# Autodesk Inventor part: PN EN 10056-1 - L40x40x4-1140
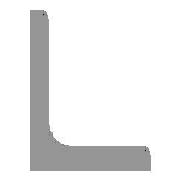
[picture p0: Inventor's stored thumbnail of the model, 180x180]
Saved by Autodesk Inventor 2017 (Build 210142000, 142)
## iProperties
IsCustomPart: 1
Created: 2020-07
Part Number: PN EN 10056-1 - L40x40x4-1140
Material: Stal, miękka
Description: Kątownik równoramienny
Document SubType Name: Modeling
Standard: PN
Designer: X
Standards Organization: PN
Language: pl-PL
Size Designation: L40x40x4
Categories: <MemberInstance><Categories><Category DisplayName="Kształtowniki konstrukcyjne" InternalName="089c4875-fa83-4c05-b084-43b9cc11f5ed" Mnemonic="GRDR"><CategoryPar
Stock Number: L40x40x4
Density: 7.85 g/cm^3
Appearance: Częściowo polerowana
Mass: 2755.06 g
Surface Area: 1771.44 cm^2
Volume: 350.964 cm^3
_CCFamilyMember: 70
_CCFamilyDisplayName: PN EN 10056-1 (Kątownik równoramienny) - Kątownik równoramienny
_FrameMemberDoc: Frame Member File
_Version: 15.0.0
_GetPNFromCC: 1
G_L: 1140,000 mm
G_W: 40,000 mm
G_H: 40,000 mm
Author: X
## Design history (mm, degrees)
node "Płaszczyzna początkowa"
node "Płaszczyzna końcowa"
sketch "Szkic2"
  geometry: L1 (-7.249, -1.249)-(-7.249, 25.751); L2 (-11.249, 28.751)-(-10.249, 28.751); L3 (-11.249, -11.249)-(-11.249, 28.751); L4 (-11.249, -11.249)-(28.751, -11.249); L5 (28.751, -10.249)-(28.751, -11.249); L6 (-1.249, -7.249)-(25.751, -7.249); L7 (0, 37.497)-(0, -19.373) reference; L8 (-19.373, 0)-(37.497, 0) reference; A1 r 6 centre (-1.249, -1.249) between (-7.249, -1.249) and (-1.249, -7.249); A2 r 3 centre (-10.249, 25.751) between (-7.249, 25.751) and (-10.249, 28.751); A3 r 3 centre (25.751, -10.249) between (28.751, -10.249) and (25.751, -7.249); 3 further points
  constraints: 12 end point, 6 point on circle, 6 point on line, 6 tangent, 3 centre point, 3 horizontal, 3 vertical, 1 equal radius
  dimensions: "d4" = 40 distance of L3.start L4.end (= b); "d6" = 40 distance of L3.start L2.start (= b); "d8" = 4 distance of point (28.751, -7.249) L4.end (= ParT); "d10" = 4 distance of L2.start point (-7.249, 28.751) (= ParT); "d17" = 6 radius of A1 (= R); "d18" = 3 radius of A2 (= R1); "d19" = 11.24871 distance between parallel lines of L8 L4 (= ex); "d20" = 11.24871 distance between parallel lines of L3 L7 (= d19)
extrude "Bryła" new body sketch "Szkic2" stored distance "d11" = 1140 (= G_L); taper "d12" = 0 deg
node "Driven Length"
  sketch "Sketch3"
    geometry: L1 (0, 0)-(10, 0) reference
    constraints: 2 end point, 1 horizontal
  workplane "Work Plane10"
  sketch "Sketch4"
    geometry: L1 (-2, 0)-(12, 0) reference; L2 (-2, 1140)-(12, 1140) reference
    dimensions: "d24" = 1140 distance between parallel lines of L1 L2 (derived)
body "Solid1"
other parameters: "b" = 40 [user parameter; used in 3 equation terms], "ParT" = 4 [user parameter; used in 3 equation terms], "R" = 6 [user parameter; used in 1 equation term], "R1" = 3 [user parameter; used in 1 equation term], "G_L" = 1140 (= d24) [user parameter; used in 1 equation term], "d7" = 4 (derived), "d9" = 4 (derived), "ex" = 11.24871 (computed from b, ParT) [user parameter; used in 1 equation term], "G_OFFSET_START" = 0 [user parameter; used in 1 equation term], "G_OFFSET_END" = 0 [user parameter; used in 1 equation term], "d21" = 0 (computed from G_OFFSET_START), "d23" = 90 deg
